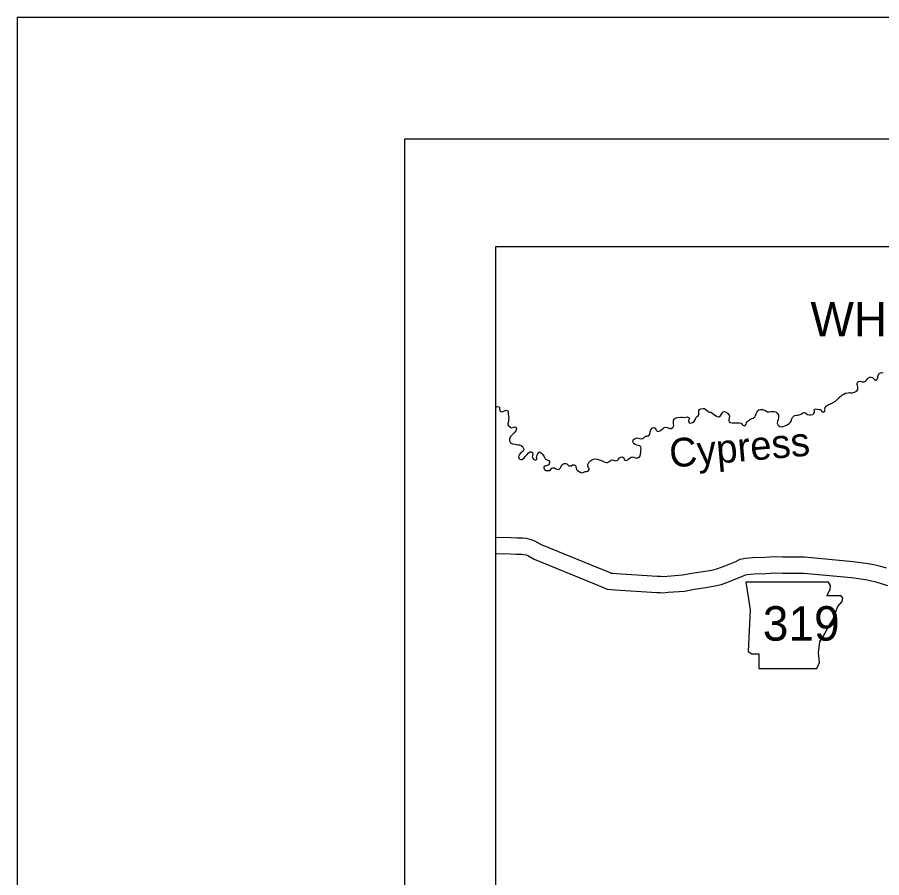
# Model space of a CAD drawing. Extents: x 1367863 to 1368197, y 380048 to 380261.
# Drawn here: x 1367863.39 to 1367891.07, y 380233.88 to 380261.43 of the extents above; entities that cross this region are included whole.
import ezdxf

# ---------------------------------------------------------------- set-up
doc = ezdxf.new("R2010")
doc.units = 0
for name, color, linetype in [('Level 10', 7, 'Continuous'), ('Level 2', 7, 'Continuous'), ('Level 21', 7, 'Continuous'), ('Level 30', 7, 'Continuous'), ('Level 9', 7, 'Continuous'), ('R_Border', 7, 'Continuous'), ('R_No Plot', 7, 'Continuous')]:
    doc.layers.add(name, color=color, linetype=linetype)

msp = doc.modelspace()

# ---------------------------------------------------------------- linework, layer by layer
at = {"layer": 'Level 10'}
for points in [[(1367878.711, 380244.783), (1367879.198, 380244.766), (1367879.386, 380244.764), (1367879.568, 380244.758), (1367879.686, 380244.748), (1367879.835, 380244.711), (1367879.951, 380244.669), (1367880.171, 380244.55), (1367882.073, 380243.766), (1367882.319, 380243.666), (1367882.413, 380243.631), (1367882.461, 380243.624), (1367882.576, 380243.614), (1367882.723, 380243.606), (1367883.888, 380243.529), (1367883.992, 380243.529), (1367884.067, 380243.526), (1367884.196, 380243.536), (1367884.692, 380243.575), (1367884.996, 380243.63), (1367885.357, 380243.68), (1367885.624, 380243.729), (1367885.794, 380243.769), (1367886.028, 380243.856), (1367886.398, 380244.006), (1367886.541, 380244.079), (1367886.707, 380244.106), (1367886.949, 380244.127), (1367887.334, 380244.145), (1367887.651, 380244.157), (1367887.897, 380244.155), (1367888.116, 380244.151), (1367888.601, 380244.154), (1367890.162, 380244.006), (1367890.634, 380243.941), (1367890.816, 380243.908), (1367891.032, 380243.854), (1367891.22, 380243.794)], [(1367878.711, 380244.26), (1367879.187, 380244.244), (1367879.375, 380244.242), (1367879.537, 380244.236), (1367879.601, 380244.231), (1367879.683, 380244.211), (1367879.736, 380244.191), (1367879.947, 380244.078), (1367881.875, 380243.283), (1367882.128, 380243.18), (1367882.284, 380243.121), (1367882.404, 380243.105), (1367882.54, 380243.093), (1367882.692, 380243.085), (1367883.87, 380243.007), (1367883.982, 380243.007), (1367884.078, 380243.003), (1367884.237, 380243.015), (1367884.759, 380243.057), (1367885.078, 380243.114), (1367885.441, 380243.164), (1367885.732, 380243.218), (1367885.946, 380243.268), (1367886.217, 380243.37), (1367886.615, 380243.531), (1367886.705, 380243.576), (1367886.772, 380243.587), (1367886.984, 380243.606), (1367887.357, 380243.623), (1367887.659, 380243.635), (1367887.89, 380243.633), (1367888.113, 380243.629), (1367888.578, 380243.631), (1367890.101, 380243.487), (1367890.551, 380243.425), (1367890.705, 380243.397), (1367890.889, 380243.351), (1367891.055, 380243.298), (1367891.254, 380243.229)]]:
    msp.add_lwpolyline(points, dxfattribs=at)
at = {"layer": 'Level 2'}
for points in [[(1367889.233, 380248.797), (1367889.253, 380248.824), (1367889.257, 380248.855), (1367889.251, 380248.881), (1367889.26, 380248.929), (1367889.292, 380248.975), (1367889.355, 380249.019), (1367889.432, 380249.051), (1367889.516, 380249.092), (1367889.593, 380249.141), (1367889.646, 380249.19), (1367889.708, 380249.255), (1367889.798, 380249.324), (1367889.855, 380249.36), (1367889.913, 380249.388), (1367889.993, 380249.408), (1367890.038, 380249.413), (1367890.071, 380249.407), (1367890.129, 380249.407), (1367890.163, 380249.413), (1367890.201, 380249.42), (1367890.242, 380249.442), (1367890.283, 380249.476), (1367890.303, 380249.514), (1367890.307, 380249.564), (1367890.306, 380249.598), (1367890.298, 380249.634), (1367890.288, 380249.669), (1367890.287, 380249.704), (1367890.295, 380249.735), (1367890.313, 380249.755), (1367890.341, 380249.768), (1367890.38, 380249.774), (1367890.422, 380249.767), (1367890.461, 380249.761), (1367890.51, 380249.761), (1367890.553, 380249.778), (1367890.6, 380249.823), (1367890.618, 380249.852), (1367890.657, 380249.893), (1367890.69, 380249.903), (1367890.732, 380249.906), (1367890.774, 380249.895), (1367890.804, 380249.861), (1367890.84, 380249.827), (1367890.872, 380249.805), (1367890.902, 380249.804), (1367890.927, 380249.833), (1367890.938, 380249.875), (1367890.959, 380249.944), (1367890.966, 380249.977), (1367890.983, 380250.008), (1367891.015, 380250.038), (1367891.062, 380250.05), (1367891.116, 380250.043)], [(1367878.711, 380248.949), (1367878.736, 380248.96), (1367878.783, 380248.967), (1367878.818, 380248.952), (1367878.831, 380248.937), (1367878.835, 380248.892), (1367878.842, 380248.85), (1367878.858, 380248.821), (1367878.896, 380248.794), (1367878.953, 380248.801), (1367878.992, 380248.823), (1367879.027, 380248.843), (1367879.046, 380248.844), (1367879.062, 380248.841), (1367879.095, 380248.823), (1367879.108, 380248.793), (1367879.106, 380248.767), (1367879.104, 380248.715), (1367879.121, 380248.663), (1367879.129, 380248.609), (1367879.124, 380248.543), (1367879.119, 380248.481), (1367879.102, 380248.421), (1367879.1, 380248.376), (1367879.132, 380248.333), (1367879.155, 380248.322), (1367879.194, 380248.297), (1367879.226, 380248.286), (1367879.276, 380248.303), (1367879.318, 380248.313), (1367879.353, 380248.305), (1367879.38, 380248.252), (1367879.358, 380248.19), (1367879.301, 380248.119), (1367879.255, 380248.075), (1367879.194, 380248.018), (1367879.153, 380247.939), (1367879.15, 380247.868), (1367879.187, 380247.804), (1367879.252, 380247.768), (1367879.336, 380247.755), (1367879.417, 380247.74), (1367879.473, 380247.733), (1367879.52, 380247.718), (1367879.566, 380247.683), (1367879.594, 380247.647), (1367879.609, 380247.596), (1367879.598, 380247.56), (1367879.551, 380247.506), (1367879.498, 380247.458), (1367879.471, 380247.429), (1367879.448, 380247.383), (1367879.441, 380247.346), (1367879.465, 380247.293), (1367879.514, 380247.266), (1367879.558, 380247.271), (1367879.621, 380247.32), (1367879.664, 380247.372), (1367879.713, 380247.431), (1367879.759, 380247.48), (1367879.812, 380247.516), (1367879.853, 380247.519), (1367879.889, 380247.498), (1367879.897, 380247.454), (1367879.885, 380247.4), (1367879.879, 380247.358), (1367879.896, 380247.309), (1367879.921, 380247.279), (1367879.962, 380247.254), (1367879.982, 380247.247), (1367880.011, 380247.257), (1367880.03, 380247.275), (1367880.03, 380247.31), (1367880.017, 380247.346), (1367880.03, 380247.39)], [(1367883.011, 380247.326), (1367883.045, 380247.348), (1367883.086, 380247.354), (1367883.137, 380247.342), (1367883.185, 380247.326), (1367883.247, 380247.321), (1367883.287, 380247.334), (1367883.321, 380247.361), (1367883.35, 380247.43), (1367883.359, 380247.504), (1367883.362, 380247.563), (1367883.364, 380247.63), (1367883.355, 380247.678), (1367883.321, 380247.702), (1367883.272, 380247.716), (1367883.225, 380247.729), (1367883.181, 380247.748), (1367883.142, 380247.773), (1367883.12, 380247.8), (1367883.106, 380247.842), (1367883.104, 380247.856), (1367883.117, 380247.896), (1367883.146, 380247.925), (1367883.178, 380247.945), (1367883.232, 380247.959), (1367883.281, 380247.955), (1367883.325, 380247.941), (1367883.37, 380247.934), (1367883.419, 380247.939), (1367883.448, 380247.955), (1367883.475, 380247.982), (1367883.485, 380247.997), (1367883.509, 380248.013), (1367883.535, 380248.021), (1367883.568, 380248.022), (1367883.597, 380248.028), (1367883.628, 380248.046), (1367883.646, 380248.083), (1367883.658, 380248.152), (1367883.68, 380248.215), (1367883.71, 380248.264), (1367883.736, 380248.282), (1367883.774, 380248.29), (1367883.816, 380248.27), (1367883.838, 380248.239), (1367883.853, 380248.207), (1367883.88, 380248.176), (1367883.906, 380248.167), (1367883.943, 380248.171), (1367883.991, 380248.2), (1367884.04, 380248.239), (1367884.076, 380248.266), (1367884.11, 380248.295), (1367884.153, 380248.307), (1367884.216, 380248.291), (1367884.258, 380248.272), (1367884.297, 380248.264), (1367884.327, 380248.263), (1367884.378, 380248.294), (1367884.397, 380248.311), (1367884.411, 380248.353), (1367884.409, 380248.416), (1367884.406, 380248.475), (1367884.408, 380248.503), (1367884.414, 380248.54), (1367884.419, 380248.561), (1367884.442, 380248.586), (1367884.478, 380248.605), (1367884.528, 380248.617), (1367884.643, 380248.627), (1367884.695, 380248.622), (1367884.744, 380248.616), (1367884.795, 380248.625), (1367884.845, 380248.63), (1367884.882, 380248.619), (1367884.905, 380248.597), (1367884.911, 380248.576), (1367884.899, 380248.551), (1367884.889, 380248.507), (1367884.89, 380248.471), (1367884.91, 380248.443), (1367884.959, 380248.431), (1367885.017, 380248.452), (1367885.063, 380248.485), (1367885.102, 380248.54), (1367885.11, 380248.566), (1367885.119, 380248.598), (1367885.136, 380248.626), (1367885.165, 380248.643), (1367885.194, 380248.665), (1367885.215, 380248.697), (1367885.22, 380248.732), (1367885.217, 380248.77), (1367885.214, 380248.803), (1367885.217, 380248.837), (1367885.236, 380248.87), (1367885.284, 380248.896), (1367885.349, 380248.902), (1367885.397, 380248.898), (1367885.453, 380248.861), (1367885.488, 380248.826)], [(1367885.488, 380248.826), (1367885.528, 380248.799), (1367885.559, 380248.788), (1367885.603, 380248.78), (1367885.621, 380248.772), (1367885.676, 380248.734), (1367885.72, 380248.697), (1367885.76, 380248.67), (1367885.8, 380248.648), (1367885.851, 380248.64), (1367885.904, 380248.664), (1367885.944, 380248.721), (1367885.961, 380248.755), (1367885.991, 380248.797), (1367886.036, 380248.808), (1367886.096, 380248.785), (1367886.149, 380248.746), (1367886.189, 380248.692), (1367886.195, 380248.654), (1367886.188, 380248.599), (1367886.179, 380248.548), (1367886.178, 380248.52), (1367886.192, 380248.477), (1367886.217, 380248.453), (1367886.28, 380248.438), (1367886.362, 380248.44), (1367886.463, 380248.443), (1367886.522, 380248.444), (1367886.569, 380248.429), (1367886.6, 380248.39), (1367886.629, 380248.367), (1367886.671, 380248.347), (1367886.702, 380248.362), (1367886.732, 380248.403), (1367886.745, 380248.44), (1367886.773, 380248.488), (1367886.807, 380248.519), (1367886.865, 380248.557), (1367886.917, 380248.58), (1367886.958, 380248.595), (1367887.006, 380248.633), (1367887.034, 380248.679), (1367887.053, 380248.729), (1367887.071, 380248.773), (1367887.096, 380248.824), (1367887.133, 380248.857), (1367887.195, 380248.869), (1367887.265, 380248.869), (1367887.314, 380248.852), (1367887.364, 380248.822), (1367887.41, 380248.797), (1367887.467, 380248.79), (1367887.54, 380248.803), (1367887.587, 380248.811), (1367887.632, 380248.807), (1367887.682, 380248.791), (1367887.728, 380248.751), (1367887.763, 380248.693), (1367887.768, 380248.635), (1367887.764, 380248.591), (1367887.753, 380248.549), (1367887.736, 380248.496), (1367887.729, 380248.435), (1367887.759, 380248.371), (1367887.809, 380248.329), (1367887.856, 380248.31), (1367887.92, 380248.322), (1367887.97, 380248.346), (1367888.042, 380248.383), (1367888.11, 380248.424), (1367888.156, 380248.46), (1367888.179, 380248.503), (1367888.187, 380248.55), (1367888.211, 380248.609), (1367888.243, 380248.648), (1367888.282, 380248.675), (1367888.338, 380248.689), (1367888.381, 380248.689), (1367888.431, 380248.699), (1367888.49, 380248.725), (1367888.543, 380248.76), (1367888.601, 380248.772), (1367888.644, 380248.751), (1367888.696, 380248.712), (1367888.745, 380248.698), (1367888.795, 380248.694), (1367888.863, 380248.71), (1367888.895, 380248.739), (1367888.919, 380248.792), (1367888.917, 380248.826), (1367888.914, 380248.857), (1367888.924, 380248.882), (1367888.964, 380248.892), (1367889.004, 380248.881), (1367889.074, 380248.871), (1367889.109, 380248.868), (1367889.135, 380248.85), (1367889.148, 380248.82), (1367889.174, 380248.793), (1367889.209, 380248.787), (1367889.233, 380248.797)], [(1367880.03, 380247.39), (1367880.053, 380247.431), (1367880.077, 380247.477), (1367880.096, 380247.502), (1367880.116, 380247.51), (1367880.145, 380247.495), (1367880.172, 380247.471), (1367880.197, 380247.449), (1367880.233, 380247.41), (1367880.256, 380247.373), (1367880.27, 380247.335), (1367880.299, 380247.292), (1367880.334, 380247.267), (1367880.378, 380247.252), (1367880.414, 380247.234), (1367880.432, 380247.205), (1367880.435, 380247.165), (1367880.424, 380247.125), (1367880.404, 380247.098), (1367880.385, 380247.083), (1367880.361, 380247.072), (1367880.335, 380247.066), (1367880.306, 380247.062), (1367880.276, 380247.054), (1367880.256, 380247.034), (1367880.248, 380247.001), (1367880.265, 380246.954), (1367880.278, 380246.933), (1367880.319, 380246.912), (1367880.392, 380246.914), (1367880.434, 380246.917), (1367880.47, 380246.936), (1367880.508, 380246.986), (1367880.537, 380247.002), (1367880.59, 380246.999), (1367880.637, 380246.974), (1367880.675, 380246.954), (1367880.708, 380246.948), (1367880.742, 380246.963), (1367880.781, 380246.999), (1367880.809, 380247.046), (1367880.832, 380247.093), (1367880.859, 380247.119), (1367880.906, 380247.139), (1367880.954, 380247.144), (1367880.993, 380247.128), (1367881.034, 380247.091), (1367881.061, 380247.069), (1367881.1, 380247.063), (1367881.129, 380247.071), (1367881.17, 380247.095), (1367881.226, 380247.102), (1367881.261, 380247.077), (1367881.281, 380247.039), (1367881.286, 380247.001), (1367881.3, 380246.952), (1367881.332, 380246.92), (1367881.38, 380246.885), (1367881.431, 380246.855), (1367881.474, 380246.842), (1367881.529, 380246.86), (1367881.57, 380246.882), (1367881.613, 380246.885), (1367881.65, 380246.893), (1367881.687, 380246.915), (1367881.702, 380246.944), (1367881.701, 380246.977), (1367881.686, 380247.006), (1367881.67, 380247.035), (1367881.657, 380247.068), (1367881.659, 380247.108), (1367881.69, 380247.17), (1367881.741, 380247.224), (1367881.782, 380247.252), (1367881.837, 380247.278), (1367881.89, 380247.285), (1367881.945, 380247.281), (1367882.066, 380247.248), (1367882.143, 380247.214), (1367882.205, 380247.186), (1367882.249, 380247.17), (1367882.291, 380247.171), (1367882.335, 380247.199), (1367882.373, 380247.229), (1367882.402, 380247.251), (1367882.434, 380247.259), (1367882.48, 380247.25), (1367882.51, 380247.234), (1367882.559, 380247.225), (1367882.602, 380247.233), (1367882.645, 380247.274), (1367882.678, 380247.317), (1367882.716, 380247.345), (1367882.756, 380247.349), (1367882.81, 380247.321), (1367882.828, 380247.273), (1367882.854, 380247.248), (1367882.898, 380247.238), (1367882.941, 380247.254), (1367882.977, 380247.292), (1367883.011, 380247.326)]]:
    msp.add_lwpolyline(points, dxfattribs=at)
at = {"layer": 'Level 21'}
msp.add_lwpolyline([(1367886.724, 380243.342), (1367886.856, 380242.458), (1367886.797, 380241.118), (1367886.915, 380241.044), (1367887.136, 380241.044), (1367887.136, 380240.573), (1367888.992, 380240.573), (1367889.08, 380240.764), (1367889.051, 380241.073), (1367889.095, 380241.427), (1367889.257, 380241.707), (1367889.36, 380241.913), (1367889.508, 380242.134), (1367889.596, 380242.369), (1367889.67, 380242.561), (1367889.802, 380242.723), (1367889.832, 380242.826), (1367889.773, 380242.9), (1367889.316, 380242.9), (1367889.419, 380243.106), (1367889.434, 380243.238), (1367889.373, 380243.34)], close=True, dxfattribs=at)
at = {"layer": 'R_Border'}
for p, q in [((1367875.8, 380257.536), (1368191.969, 380257.536)), ((1367875.8, 380052.084), (1367875.8, 380257.536))]:
    msp.add_line(p, q, dxfattribs=at)
at = {"layer": 'R_No Plot'}
for p in [(1367863.388, 380261.431), (1367863.4, 380261.431)]:
    msp.add_line(p, (1368196.721, 380261.431), dxfattribs=at)
for points in [[(1367863.393, 380261.431), (1368196.721, 380261.431), (1368196.721, 380048.101), (1367863.393, 380048.101)], [(1367878.711, 380254.093), (1367937.876, 380254.093), (1367937.876, 380187.495), (1367878.711, 380187.495)]]:
    msp.add_lwpolyline(points, close=True, dxfattribs=at)

# ---------------------------------------------------------------- texts
at = {"layer": 'Level 21'}
msp.add_text('319', height=1.1032, dxfattribs=at).set_placement((1367887.264, 380241.468))
at = {"layer": 'Level 30'}
msp.add_text('WHITE', height=1.1032, dxfattribs=at).set_placement((1367888.79, 380251.211))
at = {"layer": 'Level 9'}
msp.add_text('Cypress', height=0.9194, rotation=5, dxfattribs=at).set_placement((1367884.309, 380247.006))

doc.saveas('drawing.dxf')
